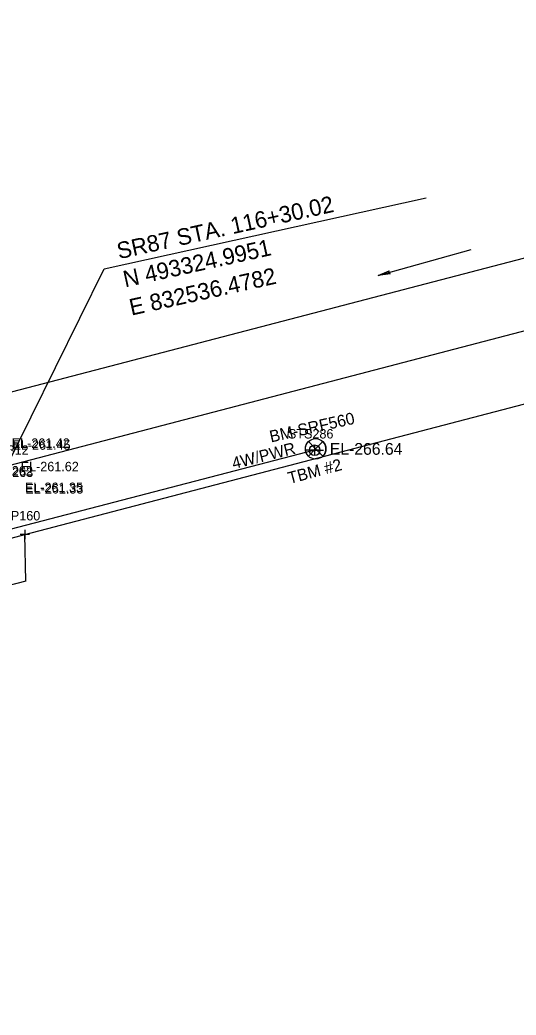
# Model space of a CAD drawing. Extents: x 818717 to 846077, y 440014 to 541392.
# Drawn here: x 832542 to 832752.7, y 493092 to 493514.4 of the extents above; entities that cross this region are included whole.
import ezdxf

# ---------------------------------------------------------------- set-up
doc = ezdxf.new("R2010")
doc.units = 0
for name, color, linetype in [('SURVEY - CENTERLINE - Preliminary Text', 7, 'Continuous'), ('SURVEY - CONTROL - Points - Elevations', 7, 'Continuous'), ('SURVEY - CONTROL with Text', 7, 'Continuous'), ('SURVEY - DRAINAGE - Area Shapes', 7, 'Continuous'), ('SURVEY - DRAINAGE - Natural Features Text', 7, 'Continuous'), ('SURVEY - DTM - Breaklines - Points - Elevations', 7, 'Continuous'), ('SURVEY - DTM - Breaklines - Points - Numbers', 7, 'Continuous'), ('SURVEY - PROPERTY - ROW Lines', 7, 'Continuous'), ('SURVEY - PROPERTY - ROW Lines - Points - Locators', 7, 'Continuous'), ('SURVEY - PROPERTY - ROW Lines - Points - Numbers', 7, 'Continuous'), ('SURVEY - PROPERTY - Station and Offset Flags', 7, 'Continuous'), ('SURVEY - TRAFFIC CONTROL - Pavement Marking - Points - Elevations', 7, 'Continuous'), ('SURVEY - TRAFFIC CONTROL - Pavement Marking - Points - Numbers', 7, 'Continuous'), ('SURVEY - TRANSPORTATION - Roads - Points - Elevations', 7, 'Continuous'), ('SURVEY - TRANSPORTATION - Roads - Points - Numbers', 7, 'Continuous'), ('SURVEY - UTILITIES - Electric (Overhead) with Text', 7, 'Continuous'), ('SURVEY - UTILITIES - Poles and Miscellaneous - Points - Locators', 7, 'Continuous'), ('SURVEY - UTILITIES - Poles and Miscellaneous - Points - Numbers', 7, 'Continuous'), ('SURVEY - UTILITIES - Poles and Miscellaneous with Text', 7, 'Continuous')]:
    doc.layers.add(name, color=color, linetype=linetype)

msp = doc.modelspace()

# ---------------------------------------------------------------- linework, layer by layer
at = {"layer": 'SURVEY - CENTERLINE - Preliminary Text'}
for p, q in [((832577.8, 493408.74), (832714.52, 493438.85)), ((832536.48, 493325), (832577.8, 493408.74))]:
    msp.add_line(p, q, dxfattribs=at)
at = {"layer": 'SURVEY - CONTROL with Text'}
for p, q in [((832664.52, 493335.41), (832667.6, 493332.33)), ((832667.6, 493332.33), (832670.68, 493335.42)), ((832664.53, 493329.27), (832667.6, 493332.33)), ((832667.6, 493332.33), (832670.67, 493329.26))]:
    msp.add_line(p, q, dxfattribs=at)
for points in [[(832664.53, 493335.4), (832667.6, 493332.33), (832664.54, 493329.28), (832664.29, 493329.53), (832664.04, 493329.86), (832663.88, 493330.11), (832663.71, 493330.42), (832663.56, 493330.76), (832663.46, 493331.03), (832663.39, 493331.29), (832663.32, 493331.58), (832663.28, 493331.87), (832663.26, 493332.13), (832663.26, 493332.46), (832663.27, 493332.73), (832663.3, 493332.98), (832663.34, 493333.17), (832663.39, 493333.4), (832663.47, 493333.68), (832663.54, 493333.89), (832663.63, 493334.12), (832663.81, 493334.46), (832664, 493334.79), (832664.29, 493335.16)], [(832670.67, 493335.41), (832667.6, 493332.33), (832670.66, 493329.26), (832670.86, 493329.46), (832671.09, 493329.74), (832671.31, 493330.07), (832671.46, 493330.32), (832671.64, 493330.73), (832671.74, 493331.01), (832671.83, 493331.3), (832671.88, 493331.54), (832671.93, 493331.86), (832671.95, 493332.11), (832671.95, 493332.42), (832671.94, 493332.73), (832671.91, 493332.94), (832671.87, 493333.22), (832671.82, 493333.41), (832671.75, 493333.67), (832671.62, 493334.03), (832671.52, 493334.23), (832671.41, 493334.45), (832671.2, 493334.8), (832670.95, 493335.13)]]:
    msp.add_lwpolyline(points, close=True, dxfattribs=at)
msp.add_circle((832667.61, 493332.35), 4.35, dxfattribs=at)
at = {"layer": 'SURVEY - DRAINAGE - Area Shapes'}
msp.add_lwpolyline([(833331.86, 493535.43), (832825.85, 493400.54), (832121.68, 493216.64), (831495.16, 493049.75), (830960.37, 492909.24), (830124.73, 492686.08), (830069.9, 493396.23), (830870.86, 494031.84), (831248.11, 494413.67), (831536.95, 494545.33), (832050.07, 494534.01), (832097.96, 494614.84), (832139.36, 494784.62), (832167.46, 494840.58), (832274.31, 494844.36), (832647.22, 494804.13), (832934.24, 494910.41), (833081.03, 494456.05), (833331.86, 493535.43)], dxfattribs=at)
at = {"layer": 'SURVEY - DRAINAGE - Natural Features Text'}
for p, q in [((832694.18, 493405.87), (832733.69, 493416.9)), ((832696.78, 493406.59), (832694.18, 493405.87))]:
    msp.add_line(p, q, dxfattribs=at)
msp.add_lwpolyline([(832694.18, 493405.87), (832698.87, 493407.85), (832698.42, 493407.05), (832699.22, 493406.6)], close=True, dxfattribs=at)
msp.add_lwpolyline([(832694.18, 493405.87), (832698.87, 493407.85), (832698.42, 493407.05), (832699.22, 493406.6), (832694.18, 493405.87)], dxfattribs=at)
at = {"layer": 'SURVEY - PROPERTY - ROW Lines'}
for p, q in [((832528.9, 493354.02), (833177.35, 493523.36)), ((832544.06, 493295.97), (833079, 493435.66)), ((832185.41, 493202.31), (832544.06, 493295.97))]:
    msp.add_line(p, q, dxfattribs=at)
at = {"layer": 'SURVEY - PROPERTY - ROW Lines - Points - Locators'}
for p, q in [((832546.06, 493295.97), (832542.06, 493295.97)), ((832544.06, 493297.97), (832544.06, 493293.97))]:
    msp.add_line(p, q, dxfattribs=at)
at = {"layer": 'SURVEY - PROPERTY - Station and Offset Flags'}
msp.add_line((832544.47, 493276.25), (832503.12, 493265.45), dxfattribs=at)
msp.add_lwpolyline([(832544.47, 493276.25), (832544.06, 493295.97)], dxfattribs=at)
at = {"layer": 'SURVEY - UTILITIES - Electric (Overhead) with Text'}
msp.add_lwpolyline([(832667.18, 493331.74), (832415.28, 493266.23), (832147.85, 493195.27), (831907.96, 493131.64), (831666.03, 493064.14), (831375.19, 492986.65), (831101.3, 492913.04)], dxfattribs=at)
at = {"layer": 'SURVEY - UTILITIES - Poles and Miscellaneous - Points - Locators'}
for p, q in [((832667.18, 493333.74), (832667.18, 493329.74)), ((832669.18, 493331.74), (832665.18, 493331.74))]:
    msp.add_line(p, q, dxfattribs=at)
at = {"layer": 'SURVEY - UTILITIES - Poles and Miscellaneous with Text'}
for q in [(832663.43, 493331.74), (832670.93, 493331.74)]:
    msp.add_line((832667.18, 493331.74), q, dxfattribs=at)
msp.add_circle((832667.18, 493331.74), 2.25, dxfattribs=at)

# ---------------------------------------------------------------- texts
at = {"layer": 'SURVEY - CENTERLINE - Preliminary Text'}
for s, p in [('SR87 STA. 116+30.02', (832584.07, 493412.81)), ('N 493324.9951', (832586.71, 493400.84)), ('E 832536.4782', (832589.34, 493388.88))]:
    msp.add_text(s, height=7, rotation=12.4223, dxfattribs=at).set_placement(p)
at = {"layer": 'SURVEY - CONTROL - Points - Elevations'}
msp.add_text('EL-266.64', height=5, dxfattribs=at).set_placement((832673.6, 493329.83))
at = {"layer": 'SURVEY - CONTROL with Text'}
for s, rotation, p in [('BM-SRF560', 12.6085, (832648.64, 493335.03)), ('TBM #2', 14.9164, (832656.57, 493317.42))]:
    msp.add_text(s, height=5, rotation=rotation, dxfattribs=at).set_placement(p)
at = {"layer": 'SURVEY - DTM - Breaklines - Points - Elevations'}
msp.add_text('EL-261.62', height=4, dxfattribs=at).set_placement((832542.34, 493322.84))
at = {"layer": 'SURVEY - DTM - Breaklines - Points - Numbers'}
msp.add_text('SRF312', height=4, dxfattribs=at).set_placement((832526.1, 493329.84))
at = {"layer": 'SURVEY - PROPERTY - ROW Lines - Points - Numbers'}
msp.add_text('SP160', height=4, dxfattribs=at).set_placement((832534.6, 493301.97))
at = {"layer": 'SURVEY - TRAFFIC CONTROL - Pavement Marking - Points - Elevations'}
for s, p in [('EL-261.45', (832538.86, 493331.96)), ('EL-261.35', (832544.1, 493314.03))]:
    msp.add_text(s, height=4, dxfattribs=at).set_placement(p)
at = {"layer": 'SURVEY - TRAFFIC CONTROL - Pavement Marking - Points - Numbers'}
msp.add_text('SRF262', height=4, dxfattribs=at).set_placement((832527.86, 493321.03))
at = {"layer": 'SURVEY - TRANSPORTATION - Roads - Points - Elevations'}
for s, p in [('EL-261.42', (832538.51, 493332.77)), ('EL-261.33', (832544.29, 493313.39))]:
    msp.add_text(s, height=4, dxfattribs=at).set_placement(p)
at = {"layer": 'SURVEY - TRANSPORTATION - Roads - Points - Numbers'}
msp.add_text('SRF263', height=4, dxfattribs=at).set_placement((832528.05, 493320.39))
at = {"layer": 'SURVEY - UTILITIES - Electric (Overhead) with Text'}
msp.add_text('4W/PWR', height=5, rotation=14.0449, dxfattribs=at).set_placement((832632.76, 493323.71))
at = {"layer": 'SURVEY - UTILITIES - Poles and Miscellaneous - Points - Numbers'}
msp.add_text('STS286', height=4, dxfattribs=at).set_placement((832655.83, 493336.74))

doc.saveas('drawing.dxf')
